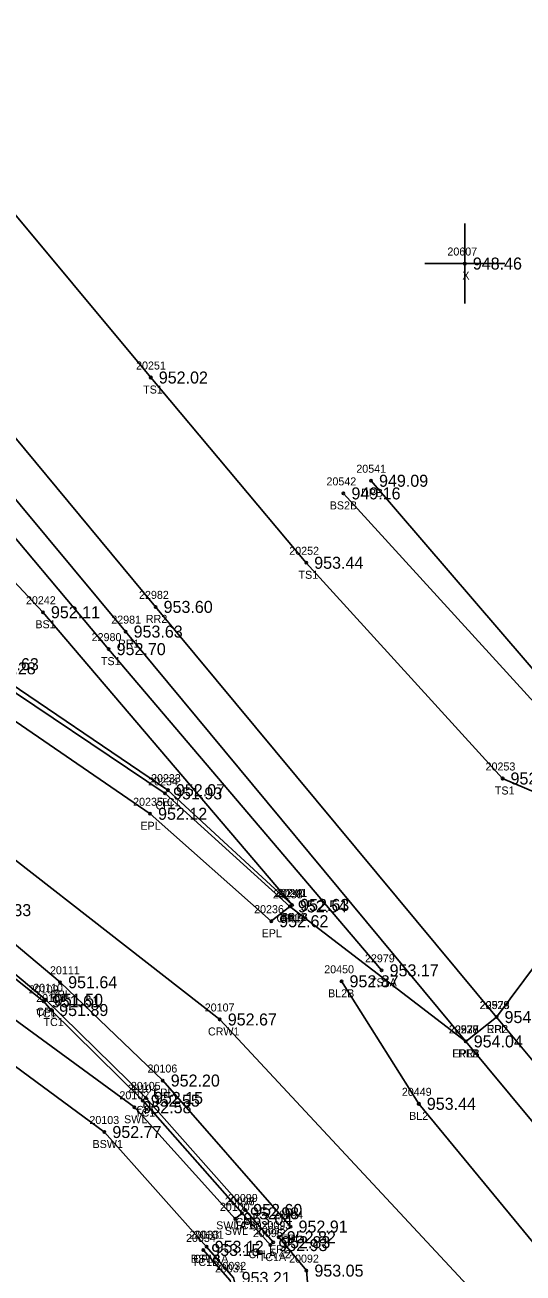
# Model space of a CAD drawing. Extents: x 1576181 to 1577685, y 1099396 to 1101490.
# Drawn here: x 1576353 to 1576415.2, y 1099611 to 1099766.9 of the extents above; entities that cross this region are included whole.
import ezdxf

# ---------------------------------------------------------------- set-up
doc = ezdxf.new("R2010")
doc.units = 0
for name, color, linetype in [('RD_DTM_BkLn1', 7, 'Continuous'), ('RD_DTM_BkLn2', 7, 'Continuous'), ('RD_DTM_BkLn_txCode', 7, 'Continuous'), ('RD_EX_Conc', 7, 'Continuous'), ('RD_EX_Conc_txCode', 7, 'Continuous'), ('RD_EX_Driveway', 7, 'Continuous'), ('RD_EX_Driveway_txCode', 7, 'Continuous'), ('RD_EX_Misc', 7, 'Continuous'), ('RD_EX_Misc_txCode', 7, 'Continuous'), ('RD_EX_RailRoad', 7, 'Continuous'), ('RD_EX_RailRoad_txCode', 7, 'Continuous'), ('RD_EX_Road', 7, 'Continuous'), ('RD_EX_Road_txCode', 7, 'Continuous'), ('RD_EX_TX_Conc_ELEV', 7, 'Continuous'), ('RD_EX_TX_Driveway_ELEV', 7, 'Continuous'), ('RD_EX_TX_Misc_ELEV', 7, 'Continuous'), ('RD_EX_TX_RailRoad_ELEV', 7, 'Continuous'), ('RD_EX_TX_Road_ELEV', 7, 'Continuous'), ('RD_HC_Survey_ELEV', 7, 'Continuous'), ('RD_HC_Survey_txCode', 7, 'Continuous'), ('RD_SMD_Locator', 7, 'Continuous')]:
    doc.layers.add(name, color=color, linetype=linetype)

msp = doc.modelspace()

# ---------------------------------------------------------------- linework, layer by layer
at = {"layer": 'RD_DTM_BkLn1'}
for points in [[(1576411.06, 1099606.41), (1576377.33, 1099642.66), (1576337.77, 1099673.47), (1576295.75, 1099700.12), (1576252.73, 1099725.71), (1576209.23, 1099750.79)], [(1576442.61, 1099587.26), (1576417.82, 1099613.19), (1576402.2, 1099632.12), (1576392.54, 1099647.43)]]:
    msp.add_lwpolyline(points, dxfattribs=at)
at = {"layer": 'RD_DTM_BkLn2'}
msp.add_line((1576418.86, 1099679.77), (1576392.78, 1099708.39), dxfattribs=at)
for points in [[(1576271.23, 1099836.06), (1576304.3, 1099797.36), (1576339.24, 1099758.21), (1576368.71, 1099722.87), (1576388.13, 1099699.72), (1576412.66, 1099672.77), (1576428.35, 1099666.09)], [(1576397.55, 1099648.8), (1576363.44, 1099688.93), (1576329.97, 1099728.73), (1576294.41, 1099771.72), (1576252.83, 1099822.18)], [(1576386.37, 1099656.97), (1576355.23, 1099693.54), (1576320.63, 1099730.47), (1576281, 1099777.41)], [(1576290.26, 1099727.95), (1576288.56, 1099723.12), (1576304.24, 1099713.85), (1576347.58, 1099687.05), (1576370.85, 1099671.31), (1576386.37, 1099656.97)], [(1576383.65, 1099614.47), (1576380.11, 1099618.44), (1576367.7, 1099632.52), (1576356.26, 1099643.84), (1576355.34, 1099644.92), (1576344.71, 1099653.36), (1576343.67, 1099654.17), (1576336.98, 1099658.63)], [(1576360.31, 1099591.7), (1576375.98, 1099605.82), (1576378.37, 1099607.89), (1576378.9, 1099608.89), (1576378.61, 1099610.06), (1576375.27, 1099613.86)]]:
    msp.add_lwpolyline(points, dxfattribs=at)
at = {"layer": 'RD_EX_Conc'}
for points in [[(1576375.69, 1099614.26), (1576362.91, 1099628.6), (1576326.83, 1099655.21), (1576295.5, 1099672.67), (1576283.88, 1099680.17), (1576241.84, 1099705.44), (1576196.96, 1099731.78)], [(1576289.77, 1099728.04), (1576287.8, 1099722.95), (1576303.93, 1099713.36), (1576347.2, 1099686.54), (1576370.5, 1099670.91), (1576386.09, 1099656.79)], [(1576380.11, 1099618.44), (1576379.26, 1099617.75), (1576366.66, 1099631.69), (1576329.19, 1099659.09), (1576302.25, 1099675.1), (1576304.48, 1099678.04)], [(1576384, 1099614.83), (1576380.5, 1099618.86), (1576368.1, 1099632.86), (1576355.6, 1099645.12), (1576345.06, 1099653.9), (1576337.3, 1099659.11)], [(1576360.94, 1099591.47), (1576368.12, 1099597.93), (1576371.83, 1099601.36), (1576376.29, 1099605.49), (1576378.65, 1099607.48), (1576379.43, 1099608.86), (1576379.06, 1099610.37), (1576375.69, 1099614.26)]]:
    msp.add_lwpolyline(points, dxfattribs=at)
at = {"layer": 'RD_EX_Driveway'}
msp.add_line((1576430.97, 1099669.47), (1576396.23, 1099709.97), dxfattribs=at)
at = {"layer": 'RD_EX_Misc'}
for p, q in [((1576407.95, 1099732.11), (1576407.95, 1099742.11)), ((1576402.95, 1099737.11), (1576412.95, 1099737.11))]:
    msp.add_line(p, q, dxfattribs=at)
at = {"layer": 'RD_EX_RailRoad'}
for points in [[(1576588.64, 1099429.74), (1576556.82, 1099468.27), (1576525.53, 1099505.93), (1576492.19, 1099546.33), (1576461.17, 1099583.65), (1576447.93, 1099599.71), (1576411.91, 1099642.96), (1576369.31, 1099694.21), (1576336.53, 1099733.7), (1576300.55, 1099777.04), (1576258.58, 1099827.59)], [(1576584.91, 1099426.47), (1576552.99, 1099465.14), (1576521.86, 1099502.63), (1576488.35, 1099543.2), (1576457.44, 1099580.52), (1576443.75, 1099596.96), (1576408.06, 1099639.92), (1576365.56, 1099691.12), (1576332.82, 1099730.47), (1576296.82, 1099773.87), (1576254.94, 1099824.3)]]:
    msp.add_lwpolyline(points, dxfattribs=at)
at = {"layer": 'RD_EX_Road'}
for points in [[(1576217.78, 1099763.81), (1576263.48, 1099736.46), (1576283.45, 1099724.57), (1576282.38, 1099722.88), (1576302.5, 1099710.8), (1576345.46, 1099684.21), (1576368.62, 1099668.36), (1576383.76, 1099654.94), (1576386.09, 1099656.79), (1576408.06, 1099639.92), (1576408.06, 1099639.92), (1576411.91, 1099642.96), (1576420.57, 1099654.58), (1576428.78, 1099665.98), (1576435.66, 1099661.47), (1576436.12, 1099661.14), (1576438.46, 1099659.42), (1576459.37, 1099692.41), (1576486.6, 1099735.59), (1576512.85, 1099776.73), (1576539.46, 1099818.98), (1576543.78, 1099825.47), (1576541.42, 1099827.15), (1576542.92, 1099831.85)], [(1576385.97, 1099603.2), (1576388.62, 1099605.88), (1576388.15, 1099611.28), (1576384.7, 1099615.46), (1576386.17, 1099616.78), (1576370.2, 1099635.03), (1576357.38, 1099647.31), (1576346.63, 1099656.32), (1576334.08, 1099664.49), (1576324.15, 1099670.38), (1576289.72, 1099690.82), (1576247.01, 1099716.05), (1576203, 1099742.27)]]:
    msp.add_lwpolyline(points, dxfattribs=at)
at = {"layer": 'RD_SMD_Locator'}
for centre in [(1576407.95, 1099737.11), (1576368.71, 1099722.87), (1576396.23, 1099709.97), (1576392.78, 1099708.39), (1576388.13, 1099699.72), (1576369.31, 1099694.21), (1576355.23, 1099693.54), (1576365.56, 1099691.12), (1576363.44, 1099688.93), (1576412.66, 1099672.77), (1576370.5, 1099670.91), (1576370.85, 1099671.31), (1576368.62, 1099668.36), (1576386.09, 1099656.79), (1576386.09, 1099656.79), (1576386.37, 1099656.97), (1576386.37, 1099656.97), (1576383.76, 1099654.94), (1576397.55, 1099648.8), (1576357.38, 1099647.31), (1576392.54, 1099647.43), (1576355.34, 1099644.92), (1576355.6, 1099645.12), (1576356.26, 1099643.84), (1576377.33, 1099642.66), (1576411.91, 1099642.96), (1576411.91, 1099642.96), (1576408.06, 1099639.92), (1576408.06, 1099639.92), (1576408.06, 1099639.92), (1576370.2, 1099635.03), (1576368.1, 1099632.86), (1576366.66, 1099631.69), (1576367.7, 1099632.52), (1576402.2, 1099632.12), (1576362.91, 1099628.6), (1576380.5, 1099618.86), (1576379.26, 1099617.75), (1576380.11, 1099618.44), (1576380.11, 1099618.44), (1576386.17, 1099616.78), (1576375.69, 1099614.26), (1576375.69, 1099614.26), (1576383.65, 1099614.47), (1576384, 1099614.83), (1576384.7, 1099615.46), (1576375.27, 1099613.86), (1576388.15, 1099611.28)]:
    msp.add_circle(centre, 0.15, dxfattribs=at)

# ---------------------------------------------------------------- texts
at = {"layer": 'RD_DTM_BkLn_txCode'}
for s, p in [('20251', (1576366.87, 1099723.87)), ('TS1', (1576367.75, 1099720.87)), ('20542', (1576390.66, 1099709.39)), ('BS2B', (1576391.07, 1099706.39)), ('20252', (1576386.01, 1099700.72)), ('TS1', (1576387.17, 1099697.72)), ('20242', (1576353.11, 1099694.54)), ('BS1', (1576354.29, 1099691.54)), ('22980', (1576361.32, 1099689.93)), ('TS1', (1576362.48, 1099686.93)), ('20253', (1576410.54, 1099673.77)), ('TS1', (1576411.7, 1099670.77)), ('20241', (1576384.53, 1099657.97)), ('BS1A', (1576384.93, 1099654.97)), ('22979', (1576395.47, 1099649.8)), ('20450', (1576390.38, 1099648.43)), ('TS1A', (1576396.1, 1099646.8)), ('BL2B', (1576390.86, 1099645.43)), ('20449', (1576400.08, 1099633.12)), ('BL2', (1576400.99, 1099630.12))]:
    msp.add_text(s, height=1, dxfattribs=at).set_placement(p)
at = {"layer": 'RD_EX_Conc_txCode'}
for s, p in [('20234', (1576368.38, 1099671.91)), ('20233', (1576368.74, 1099672.31)), ('CFL', (1576369.3, 1099668.91)), ('TC1', (1576369.89, 1099669.31)), ('20237', (1576383.97, 1099657.79)), ('20240', (1576384.21, 1099657.97)), ('CFLB', (1576384.42, 1099654.79)), ('TC1B', (1576384.93, 1099654.97)), ('20110', (1576354.01, 1099646.12)), ('20109', (1576353.47, 1099645.92)), ('20108', (1576354.38, 1099644.84)), ('TC1', (1576354.38, 1099642.92)), ('CFL', (1576354.4, 1099643.12)), ('TC1', (1576355.3, 1099641.84)), ('20104', (1576365.83, 1099633.52)), ('20105', (1576366.22, 1099633.86)), ('20102', (1576364.79, 1099632.69)), ('TC1', (1576366.74, 1099630.52)), ('CFL', (1576366.89, 1099630.86)), ('20103', (1576361.04, 1099629.6)), ('SWL', (1576365.37, 1099629.69)), ('BSW1', (1576361.43, 1099626.6)), ('20099', (1576378.35, 1099619.86)), ('20100', (1576377.34, 1099618.75)), ('20097', (1576377.96, 1099619.44)), ('20098', (1576377.96, 1099619.44)), ('SWLA 60', (1576376.88, 1099616.44)), ('TC1', (1576379.15, 1099616.44)), ('CFL', (1576379.3, 1099616.86)), ('20034', (1576373.11, 1099614.86)), ('20033', (1576373.54, 1099615.26)), ('20101', (1576374.1, 1099615.26)), ('SWL', (1576377.96, 1099615.75)), ('20096', (1576381.47, 1099615.47)), ('20095', (1576381.84, 1099615.83)), ('BSW1A', (1576373.72, 1099612.26)), ('TC1B', (1576373.84, 1099611.86)), ('CFLB', (1576374.02, 1099612.26)), ('CFLA 42', (1576380.92, 1099612.83)), ('TC1A', (1576382.2, 1099612.47)), ('20031', (1576376.73, 1099611.06)), ('20032', (1576376.91, 1099611.37))]:
    msp.add_text(s, height=1, dxfattribs=at).set_placement(p)
at = {"layer": 'RD_EX_Driveway_txCode'}
for s, p in [('20541', (1576394.39, 1099710.97)), ('DPB', (1576394.97, 1099707.97))]:
    msp.add_text(s, height=1, dxfattribs=at).set_placement(p)
at = {"layer": 'RD_EX_Misc_txCode'}
for s, p in [('20607', (1576405.77, 1099738.11)), ('X', (1576407.64, 1099735.11))]:
    msp.add_text(s, height=1, dxfattribs=at).set_placement(p)
at = {"layer": 'RD_EX_RailRoad_txCode'}
for s, p in [('22982', (1576367.24, 1099695.21)), ('22981', (1576363.77, 1099692.12)), ('RR2', (1576368.09, 1099692.21)), ('RR1', (1576364.62, 1099689.12)), ('22978', (1576409.83, 1099643.96)), ('22977', (1576405.98, 1099640.92)), ('RR2', (1576410.68, 1099640.96)), ('RR1', (1576407.12, 1099637.92))]:
    msp.add_text(s, height=1, dxfattribs=at).set_placement(p)
at = {"layer": 'RD_EX_Road_txCode'}
for s, p in [('20235', (1576366.5, 1099669.36)), ('EPL', (1576367.41, 1099666.36)), ('20238', (1576383.97, 1099657.79)), ('20236', (1576381.62, 1099655.94)), ('EPL', (1576384.89, 1099654.79)), ('EPL', (1576382.56, 1099652.94)), ('20111', (1576356.11, 1099648.31)), ('EPL', (1576356.17, 1099645.31)), ('20529', (1576409.79, 1099643.96)), ('20239', (1576405.94, 1099640.92)), ('20528', (1576405.94, 1099640.92)), ('EPL', (1576410.71, 1099640.96)), ('EPLA', (1576406.37, 1099637.92)), ('EPLB', (1576406.39, 1099637.92)), ('20106', (1576368.3, 1099636.03)), ('EPL', (1576369, 1099633.03)), ('20093', (1576382.54, 1099616.46)), ('20094', (1576384.01, 1099617.78)), ('EPL', (1576383.49, 1099613.46)), ('EPL', (1576384.96, 1099614.78)), ('20092', (1576385.99, 1099612.28))]:
    msp.add_text(s, height=1, dxfattribs=at).set_placement(p)
at = {"layer": 'RD_EX_TX_Conc_ELEV'}
for s, p in [('951.63', (1576348.58, 1099686.3)), ('951.28', (1576348.2, 1099685.79)), ('952.07', (1576371.85, 1099670.56)), ('951.93', (1576371.5, 1099670.16)), ('952.54', (1576387.09, 1099656.04)), ('952.63', (1576387.37, 1099656.22)), ('951.61', (1576356.34, 1099644.17)), ('951.50', (1576356.6, 1099644.37)), ('951.89', (1576357.26, 1099643.09)), ('952.55', (1576368.7, 1099631.77)), ('952.15', (1576369.1, 1099632.11)), ('952.58', (1576367.66, 1099630.94)), ('952.77', (1576363.91, 1099627.85)), ('952.98', (1576381.11, 1099617.69)), ('952.98', (1576381.11, 1099617.69)), ('952.60', (1576381.5, 1099618.11)), ('953.04', (1576380.26, 1099617)), ('953.15', (1576376.27, 1099613.11)), ('953.12', (1576376.69, 1099613.51)), ('953.12', (1576376.69, 1099613.51)), ('952.93', (1576384.65, 1099613.72)), ('952.83', (1576385, 1099614.08)), ('953.21', (1576380.06, 1099609.62))]:
    msp.add_text(s, height=1.5, dxfattribs=at).set_placement(p)
at = {"layer": 'RD_EX_TX_Driveway_ELEV'}
msp.add_text('949.09', height=1.5, dxfattribs=at).set_placement((1576397.23, 1099709.22))
at = {"layer": 'RD_EX_TX_Misc_ELEV'}
for s, p in [('948.46', (1576408.95, 1099736.36)), ('952.02', (1576369.71, 1099722.12)), ('949.16', (1576393.78, 1099707.64)), ('953.44', (1576389.13, 1099698.97)), ('952.11', (1576356.23, 1099692.79)), ('952.70', (1576364.44, 1099688.18)), ('952.85', (1576413.66, 1099672.02)), ('952.63', (1576387.37, 1099656.22)), ('953.17', (1576398.55, 1099648.05)), ('952.87', (1576393.54, 1099646.68)), ('953.44', (1576403.2, 1099631.37))]:
    msp.add_text(s, height=1.5, dxfattribs=at).set_placement(p)
at = {"layer": 'RD_EX_TX_RailRoad_ELEV'}
for s, p in [('953.60', (1576370.31, 1099693.46)), ('953.63', (1576366.56, 1099690.37)), ('954.04', (1576412.91, 1099642.21)), ('954.04', (1576409.06, 1099639.17))]:
    msp.add_text(s, height=1.5, dxfattribs=at).set_placement(p)
at = {"layer": 'RD_EX_TX_Road_ELEV'}
for s, p in [('952.12', (1576369.62, 1099667.61)), ('951.33', (1576347.63, 1099655.57)), ('952.54', (1576387.09, 1099656.04)), ('952.62', (1576384.76, 1099654.19)), ('951.64', (1576358.38, 1099646.56)), ('954.04', (1576412.91, 1099642.21)), ('954.04', (1576409.06, 1099639.17)), ('954.04', (1576409.06, 1099639.17)), ('952.20', (1576371.2, 1099634.28)), ('952.91', (1576387.17, 1099616.03)), ('952.82', (1576385.7, 1099614.71)), ('953.05', (1576389.15, 1099610.53))]:
    msp.add_text(s, height=1.5, dxfattribs=at).set_placement(p)
at = {"layer": 'RD_HC_Survey_ELEV'}
msp.add_text('952.67', height=1.5, dxfattribs=at).set_placement((1576378.33, 1099641.91))
at = {"layer": 'RD_HC_Survey_txCode'}
for s, p in [('20107', (1576375.45, 1099643.66)), ('CRW1', (1576375.85, 1099640.66))]:
    msp.add_text(s, height=1, dxfattribs=at).set_placement(p)

doc.saveas('drawing.dxf')
